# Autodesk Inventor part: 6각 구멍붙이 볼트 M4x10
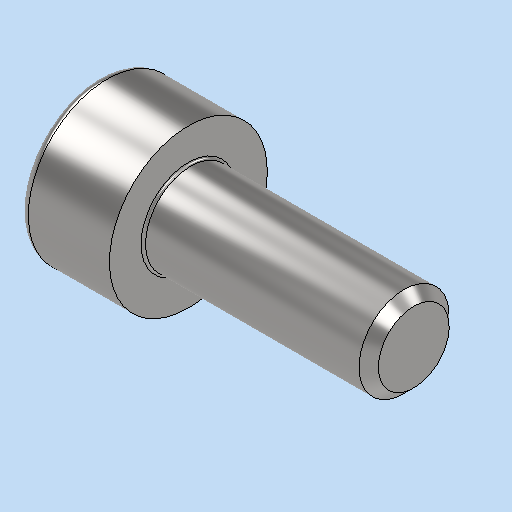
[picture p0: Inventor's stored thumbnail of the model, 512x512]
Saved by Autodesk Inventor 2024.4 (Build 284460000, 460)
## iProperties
Created: 2025-11
Part Number: 6각 구멍붙이 볼트 M4x10
Material: 강철, 연강
Description: 6각머리 태핑 나사
Document SubType Name: Modeling
Designer: home
Density: 7.85 g/cm^3
Appearance: 기본값
Author: jhkim
Sending System: Autodesk Inventor 2026
Preprocessor: ST-DEVELOPER v20.1
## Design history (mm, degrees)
feature "Solid1"
node "솔리드1"
